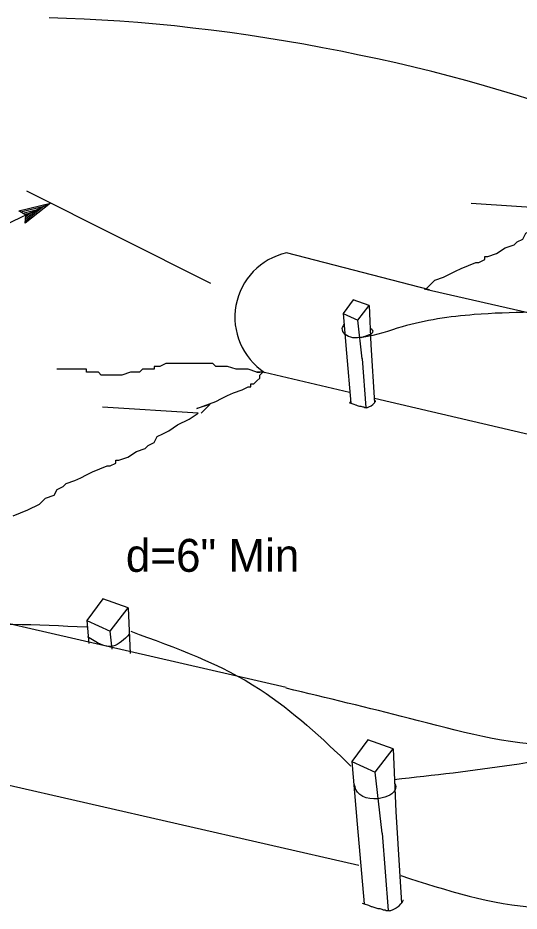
# Model space of a CAD drawing. Extents: x 6707415 to 6708768, y 1869893 to 1870831.
# Drawn here: x 6707644.1 to 6707735.5, y 1870195.5 to 1870358.4 of the extents above; entities that cross this region are included whole.
import ezdxf

# ---------------------------------------------------------------- set-up
doc = ezdxf.new("R2010")
doc.units = 0
for name, color, linetype in [('56 Stg 3 Anno', 7, 'Continuous'), ('57 Undefined', 7, 'Continuous'), ('60 Nongeo Data', 7, 'Continuous')]:
    doc.layers.add(name, color=color, linetype=linetype)

msp = doc.modelspace()

# ---------------------------------------------------------------- linework, layer by layer
at = {"layer": '56 Stg 3 Anno'}
for p, q in [((6707679.29, 1870309.93), (6707645.77, 1870326.75)), ((6707543.17, 1870273.7), (6707650.06, 1870324.6)), ((6707644.32, 1870323.21), (6707650.06, 1870324.6)), ((6707644.66, 1870323), (6707648.87, 1870324.01)), ((6707650.06, 1870324.6), (6707645.46, 1870320.91)), ((6707648.86, 1870324.01), (6707645.51, 1870321.32)), ((6707650.06, 1870324.6), (6707650.06, 1870324.6)), ((6707645.58, 1870322.4), (6707644.32, 1870323.21)), ((6707644.32, 1870323.21), (6707644.32, 1870323.21)), ((6707645.01, 1870322.78), (6707647.68, 1870323.43)), ((6707645.31, 1870322.56), (6707646.49, 1870322.85)), ((6707645.46, 1870320.91), (6707645.58, 1870322.4)), ((6707647.68, 1870323.43), (6707645.51, 1870321.69)), ((6707646.49, 1870322.85), (6707645.56, 1870322.1)), ((6707645.46, 1870320.91), (6707645.46, 1870320.91))]:
    msp.add_line(p, q, dxfattribs=at)
msp.add_ellipse((6707692.49, 1870326.8), major_axis=(94.95, -17.15), ratio=0.279834, start_param=0.934096, end_param=2.086505, dxfattribs=at)
at = {"layer": '60 Nongeo Data'}
for p, q in [((6707719.18, 1870308.76), (6707693.08, 1870315.51)), ((6707718.18, 1870308.99), (6707780.25, 1870294.75)), ((6707708.15, 1870305.92), (6707708.46, 1870298.74)), ((6707706.91, 1870296.22), (6707707.58, 1870287.34)), ((6707689.09, 1870293.74), (6707704.6, 1870290.1)), ((6707704.85, 1870288.09), (6707704.62, 1870288.38)), ((6707709.15, 1870289.03), (6707771.34, 1870274.43)), ((6707693.04, 1870236.28), (6707630.27, 1870250.69)), ((6707664.23, 1870250.79), (6707664.59, 1870242.49)), ((6707605.27, 1870226.96), (6707706.29, 1870203.89)), ((6707712.53, 1870225.08), (6707713.02, 1870213.68)), ((6707710.56, 1870209.68), (6707711.62, 1870195.61))]:
    msp.add_line(p, q, dxfattribs=at)
for points in [[(6707718.5, 1870308.92), (6707720.15, 1870310.57), (6707721.75, 1870311.1), (6707722.82, 1870311.63), (6707723.89, 1870312.17), (6707724.96, 1870312.7), (6707727.64, 1870313.77), (6707728.18, 1870313.77), (6707729.25, 1870314.31), (6707729.25, 1870314.84), (6707729.78, 1870314.84), (6707731.39, 1870315.38), (6707732.99, 1870316.45), (6707734.6, 1870316.98), (6707735.13, 1870317.51), (6707736.2, 1870318.05), (6707736.74, 1870319.12), (6707737.81, 1870319.65), (6707738.88, 1870320.19), (6707740.49, 1870321.26), (6707742.63, 1870322.32), (6707744.23, 1870323.39), (6707726.78, 1870324.51)], [(6707703.4, 1870304.47), (6707704.02, 1870297.25)], [(6707706.88, 1870296.23), (6707706.91, 1870296.22), (6707706.09, 1870303.23)], [(6707708.46, 1870298.74), (6707709.13, 1870288.17)], [(6707704.02, 1870297.25), (6707704.85, 1870288.09)], [(6707687.69, 1870293.76), (6707686.09, 1870294.3), (6707685.55, 1870294.3), (6707685.02, 1870294.3), (6707683.94, 1870294.3), (6707682.34, 1870294.83), (6707680.2, 1870294.83), (6707679.66, 1870295.37), (6707679.13, 1870295.37), (6707678.06, 1870295.37), (6707676.99, 1870295.37), (6707676.45, 1870295.37), (6707675.92, 1870295.37), (6707675.38, 1870295.37), (6707674.84, 1870295.37), (6707674.31, 1870295.37), (6707673.24, 1870295.37), (6707672.7, 1870295.37), (6707671.63, 1870295.37), (6707671.1, 1870295.37), (6707670.03, 1870294.83), (6707668.96, 1870294.83), (6707668.96, 1870294.3), (6707667.35, 1870294.3), (6707666.82, 1870294.3), (6707666.28, 1870293.76), (6707665.75, 1870293.76), (6707664.68, 1870293.76), (6707663.07, 1870293.23), (6707662.53, 1870293.23), (6707661.46, 1870293.23), (6707660.39, 1870293.23), (6707659.32, 1870293.23), (6707658.79, 1870293.76), (6707657.18, 1870293.76), (6707656.65, 1870293.76), (6707656.65, 1870294.3), (6707655.58, 1870294.3), (6707654.51, 1870294.3), (6707653.97, 1870294.3), (6707653.43, 1870294.3), (6707651.83, 1870294.3), (6707651.2, 1870294.3)], [(6707677.52, 1870286.28), (6707678.59, 1870287.35), (6707679.13, 1870287.88), (6707676.72, 1870287.17), (6707680.2, 1870288.42), (6707681.27, 1870288.95), (6707682.34, 1870289.49), (6707683.41, 1870290.02), (6707685.02, 1870290.56), (6707686.09, 1870291.09), (6707686.62, 1870291.09), (6707686.62, 1870291.63), (6707687.16, 1870291.63), (6707687.69, 1870292.16), (6707688.23, 1870292.7), (6707688.23, 1870293.23), (6707688.76, 1870293.76), (6707688.23, 1870293.76), (6707687.69, 1870293.76), (6707688.23, 1870293.76)], [(6707704.59, 1870288.18), (6707704.81, 1870288.1), (6707705.35, 1870287.95), (6707705.65, 1870287.8), (6707705.73, 1870287.8), (6707705.95, 1870287.72), (6707706.18, 1870287.65), (6707706.41, 1870287.57), (6707706.64, 1870287.57), (6707706.86, 1870287.5), (6707707.01, 1870287.42), (6707707.24, 1870287.42), (6707707.32, 1870287.34), (6707707.39, 1870287.34), (6707707.7, 1870287.34), (6707707.77, 1870287.27), (6707707.85, 1870287.34), (6707708.08, 1870287.42), (6707708.55, 1870287.65)], [(6707708.53, 1870287.65), (6707708.84, 1870287.87), (6707709.06, 1870288.1), (6707709.14, 1870288.18), (6707709.21, 1870288.25), (6707709.29, 1870288.48), (6707709.37, 1870288.48), (6707709.37, 1870288.48), (6707709.29, 1870288.48)], [(6707643.27, 1870267.57), (6707645.94, 1870268.64), (6707648.08, 1870269.71), (6707649.15, 1870270.78), (6707650.76, 1870271.32), (6707651.29, 1870272.38), (6707652.36, 1870272.92), (6707652.9, 1870273.45), (6707654.51, 1870273.99), (6707655.58, 1870274.52), (6707656.65, 1870275.06), (6707657.72, 1870275.59), (6707660.39, 1870276.66), (6707660.93, 1870276.66), (6707662, 1870277.2), (6707662, 1870277.73), (6707662.53, 1870277.73), (6707664.14, 1870278.26), (6707665.75, 1870279.33), (6707667.35, 1870279.87), (6707667.89, 1870280.4), (6707668.96, 1870280.94), (6707669.49, 1870282.01), (6707670.56, 1870282.54), (6707671.63, 1870283.07), (6707673.24, 1870284.14), (6707675.38, 1870285.21), (6707676.99, 1870286.28), (6707659.54, 1870287.4)], [(6707656.69, 1870248.5), (6707657.05, 1870244.29)], [(6707661.34, 1870243.27), (6707660.95, 1870246.53)], [(6707704.98, 1870222.78), (6707705.97, 1870211.32)], [(6707710.51, 1870209.7), (6707710.56, 1870209.68), (6707709.25, 1870220.82)], [(6707713.02, 1870213.68), (6707714.08, 1870196.92)], [(6707705.97, 1870211.32), (6707707.28, 1870196.79)], [(6707706.87, 1870196.93), (6707707.23, 1870196.81), (6707708.07, 1870196.57), (6707708.55, 1870196.33), (6707708.67, 1870196.33), (6707709.03, 1870196.21), (6707709.39, 1870196.09), (6707709.75, 1870195.97), (6707710.12, 1870195.97), (6707710.48, 1870195.85), (6707710.72, 1870195.73), (6707711.08, 1870195.73), (6707711.2, 1870195.61), (6707711.32, 1870195.61), (6707711.8, 1870195.61), (6707711.92, 1870195.49), (6707712.04, 1870195.61), (6707712.4, 1870195.73), (6707713.15, 1870196.09)], [(6707713.12, 1870196.09), (6707713.61, 1870196.45), (6707713.97, 1870196.81), (6707714.09, 1870196.93), (6707714.21, 1870197.05), (6707714.33, 1870197.41), (6707714.45, 1870197.41), (6707714.45, 1870197.41), (6707714.33, 1870197.41)]]:
    msp.add_lwpolyline(points, dxfattribs=at)
for points in [[(6707703.4, 1870304.47), (6707706.09, 1870303.23), (6707708.15, 1870305.92), (6707705.26, 1870306.95)], [(6707656.69, 1870248.5), (6707660.95, 1870246.53), (6707664.23, 1870250.79), (6707659.64, 1870252.43)], [(6707704.98, 1870222.78), (6707709.25, 1870220.82), (6707712.53, 1870225.08), (6707707.94, 1870226.71)]]:
    msp.add_lwpolyline(points, close=True, dxfattribs=at)
msp.add_arc((6707695.72, 1870303.77), 12.03, 102.7086, 236.5226, dxfattribs=at)
for points in [[(6707744.12, 1870304.74), (6707737.51, 1870304.68), (6707727.34, 1870304.26), (6707714.16, 1870302.03), (6707706.88, 1870300.11), (6707703.75, 1870300.71), (6707703.27, 1870301.73), (6707703.63, 1870302.45)], [(6707706.74, 1870300.1), (6707708.78, 1870301.4), (6707708.46, 1870301.65)], [(6707596.58, 1870244.84), (6707596.19, 1870244.06), (6707601.24, 1870242.77), (6707631.03, 1870247.3), (6707656.67, 1870247.3)], [(6707664.44, 1870246), (6707661.46, 1870243.81), (6707656.8, 1870245.49)], [(6707664.7, 1870246.52), (6707688.27, 1870235.92), (6707704.85, 1870221.95)], [(6707767.96, 1870229.96), (6707742.38, 1870225.71), (6707715.5, 1870230.62), (6707693.04, 1870236.13)], [(6707712.75, 1870219.5), (6707755.22, 1870226.48), (6707783.85, 1870236.69)], [(6707712.88, 1870218.72), (6707713, 1870218.2), (6707710.54, 1870216.13), (6707705.75, 1870217.69), (6707705.49, 1870218.59)], [(6707713.94, 1870201.96), (6707738.84, 1870196.15), (6707773.53, 1870202.48)]]:
    msp.add_spline(points, degree=3, dxfattribs=at)

# ---------------------------------------------------------------- texts
at = {"layer": '57 Undefined'}
msp.add_text('d=6" Min', height=6, dxfattribs=at).set_placement((6707663.81, 1870257.36))

doc.saveas('drawing.dxf')
